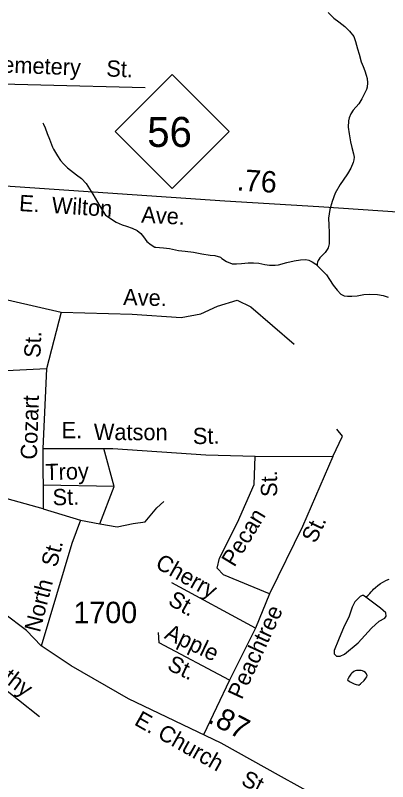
# Model space of a CAD drawing. Extents: x 2056842 to 2160602, y 826753 to 1016856.
# Drawn here: x 2093495 to 2095668, y 860118 to 864586 of the extents above; entities that cross this region are included whole.
import ezdxf

# ---------------------------------------------------------------- set-up
doc = ezdxf.new("R2010")
doc.units = 0
for name, color, linetype in [('Exist Hydrographic Creek Single Shore', 7, 'Continuous'), ('Exist Hydrographic Misc Water Feature', 7, 'Continuous'), ('Exist Road Non-System Type 51', 7, 'Continuous'), ('Exist Road Non-System Type 51 Label', 7, 'Continuous'), ('Exist Road Primary NC Attributed', 7, 'Continuous'), ('Exist Road Primary NC Label', 7, 'Continuous'), ('Exist Road Primary NC Service Mileage Hundredths English Label', 7, 'Continuous'), ('Exist Road Primary NC Shield CELL', 7, 'Continuous'), ('Exist Road Primary NC Shield Number Label', 7, 'Continuous'), ('Exist Road Secondary Mileage Hundredths English Label', 7, 'Continuous'), ('Exist Road Secondary Type 51 Attributed', 7, 'Continuous'), ('Exist Road Secondary Type 51 Label', 7, 'Continuous'), ('Exist Road Secondary Type 51 Number Label', 7, 'Continuous')]:
    doc.layers.add(name, color=color, linetype=linetype)

msp = doc.modelspace()

# ---------------------------------------------------------------- linework, layer by layer
at = {"layer": 'Exist Hydrographic Creek Single Shore'}
for points in [[(2095320, 864601.7), (2095337.8, 864584.4), (2095353.4, 864568.7), (2095383.4, 864549.1), (2095417.4, 864521.2), (2095445.5, 864493.4), (2095469.9, 864463.4), (2095480.1, 864433.4), (2095491.8, 864391.4), (2095502.3, 864359.4), (2095514.2, 864315.9), (2095524.2, 864287.6), (2095534.5, 864261.6), (2095542.3, 864237.7), (2095548.8, 864217.6), (2095550.9, 864191.8), (2095548.8, 864167.7), (2095544.9, 864153.8), (2095531, 864125.9), (2095517.3, 864099.5), (2095499, 864069.4), (2095467, 864033.7), (2095453.3, 864011.5), (2095443.2, 863989.4), (2095439.3, 863971.4), (2095437.7, 863933.4), (2095443.6, 863895.6), (2095451.6, 863849.4), (2095459.6, 863815.6), (2095468, 863779.5), (2095471.9, 863759.4), (2095470.1, 863743.5), (2095466.2, 863727.5), (2095452.5, 863695.5), (2095434, 863661.7), (2095408.4, 863625.4), (2095390.5, 863599.3), (2095362.6, 863549.2), (2095343.2, 863501.4), (2095331.3, 863454.9), (2095323.1, 863403.1), (2095325.3, 863363.3), (2095327.4, 863319.2), (2095327.6, 863285.1), (2095325.7, 863253.3), (2095321.6, 863231.2), (2095315.7, 863221.2), (2095303.8, 863203), (2095281.7, 863182.8), (2095272, 863173), (2095266.1, 863163), (2095262, 863157), (2095257.9, 863147.2), (2095256, 863138.9), (2095256.2, 863127.1)], [(2093655.6, 863960.1), (2093659.9, 863952.1), (2093669.7, 863929.9), (2093681.8, 863898.1), (2093694.1, 863864.1), (2093712.2, 863818), (2093717.9, 863806.2), (2093740.3, 863766.3), (2093758.5, 863740.4), (2093776.4, 863720.2), (2093800.4, 863696.3), (2093852.4, 863656.7), (2093880.5, 863634.7), (2093908.8, 863604.8), (2093947, 863543), (2093989.2, 863472.9), (2094021, 863421), (2094083.1, 863381.1), (2094119.2, 863365.5), (2094143.4, 863357.4), (2094177.4, 863345.3), (2094205.3, 863331.8), (2094227.5, 863313.9), (2094243.7, 863294), (2094261.9, 863268), (2094288, 863247.8), (2094309.9, 863234), (2094315.7, 863233.9), (2094335.7, 863232.1), (2094359.7, 863230.1), (2094395.6, 863226.3), (2094448.1, 863214.3), (2094485.6, 863210.6), (2094534, 863204.5), (2094583.9, 863194.9), (2094631.8, 863187.2), (2094659.9, 863185), (2094691.9, 863175.3), (2094699.7, 863169.2), (2094728.2, 863151.6), (2094759.8, 863137.4), (2094786.2, 863137.4), (2094816, 863139.5), (2094854.1, 863143.8), (2094884.3, 863143.7), (2094916.2, 863142.1), (2094951.7, 863133.8), (2094978, 863130.3), (2094991.9, 863130.2), (2095012, 863130.5), (2095030.1, 863132.2), (2095080.3, 863144.4), (2095121.7, 863154.3), (2095159.9, 863160.8), (2095190, 863162.7), (2095207.8, 863158.7), (2095227.9, 863148.8), (2095248.2, 863134.9), (2095256.2, 863127.1)], [(2095256.2, 863127.1), (2095280, 863104.8), (2095310.2, 863073), (2095328.4, 863045.1), (2095350.3, 863013.5), (2095374.1, 862983.4), (2095394.2, 862961.3), (2095414.3, 862951.3), (2095434.4, 862949.6), (2095458.6, 862949.5), (2095490.4, 862951.6), (2095528.5, 862958), (2095564.4, 862959.8), (2095608.3, 862958.1), (2095642.7, 862952.1), (2095670.2, 862942.2)]]:
    msp.add_lwpolyline(points, dxfattribs=at)
at = {"layer": 'Exist Hydrographic Misc Water Feature'}
for points in [[(2095539.8, 861194), (2095554.2, 861206.1), (2095563.8, 861216), (2095571.6, 861224.2), (2095579.8, 861232.3), (2095585.7, 861240.3), (2095598, 861250.2), (2095611.6, 861262.3), (2095625.9, 861274.3), (2095639.5, 861282.4), (2095661.6, 861292.5), (2095677.4, 861298.6)], [(2095539.8, 861194), (2095527.3, 861204.1), (2095518.4, 861204.1), (2095507, 861197.8), (2095476.7, 861167.4), (2095460.2, 861135.7), (2095441.2, 861077.5), (2095413.3, 861024.2), (2095380.4, 860944.4), (2095355.1, 860882.3), (2095355.1, 860863.3), (2095369, 860849.4), (2095391.8, 860849.4), (2095415.9, 860862.1), (2095495.6, 860928), (2095572.9, 861012.8), (2095618.5, 861053.4), (2095651.4, 861071.1), (2095659, 861083.8), (2095656.5, 861102.8), (2095626.1, 861129.4), (2095539.8, 861194)], [(2095499.1, 860680.5), (2095509, 860688.7), (2095530.9, 860708.5), (2095541, 860722.4), (2095546.5, 860730.5), (2095548.8, 860736.7), (2095546.5, 860740.7), (2095544.5, 860746.6), (2095538.7, 860754.8), (2095528.5, 860760.3), (2095520.7, 860764.4), (2095512.7, 860766.5), (2095504.5, 860766.5), (2095496.9, 860766.4), (2095486.6, 860766.3), (2095478.6, 860764.3), (2095470.8, 860760.7), (2095459, 860750.3), (2095452.8, 860744.3), (2095444.8, 860734.1), (2095436.8, 860720.4), (2095433.1, 860712.4), (2095445, 860702.4), (2095460.6, 860694.4), (2095472.9, 860688.5), (2095485, 860684.7), (2095494.8, 860682.7), (2095499.1, 860680.5)]]:
    msp.add_lwpolyline(points, dxfattribs=at)
at = {"layer": 'Exist Road Non-System Type 51'}
for p, q in [((2093763.4, 862855.8), (2093677.2, 862524.3)), ((2093677.2, 862524.3), (2093656.4, 862060.8)), ((2093656.4, 862060.8), (2093658.5, 861709.6)), ((2094072.8, 861839.5), (2094011.9, 862060.8)), ((2094895.3, 862016.1), (2095347.1, 862015.1)), ((2093987.7, 861621.2), (2094072.8, 861839.5)), ((2093658.5, 861709.6), (2093875.5, 861642)), ((2093875.5, 861642), (2093987.7, 861621.2)), ((2094897.4, 861014.3), (2094409.3, 861278.3)), ((2094978.4, 861213.9), (2094897.4, 861014.3)), ((2094897.4, 861014.3), (2094745.8, 860710.9)), ((2093248.4, 860803.6), (2093635.8, 860499)), ((2094745.8, 860710.9), (2094593.4, 860391.4))]:
    msp.add_line(p, q, dxfattribs=at)
for points in [[(2094253.6, 864164.4), (2093032.2, 864194.9)], [(2092618.3, 863100.9), (2093066.5, 863014.8), (2093763.4, 862855.8)], [(2093763.4, 862855.8), (2094177.7, 862844.4), (2094462.3, 862823.6), (2094577.5, 862845.4), (2094675.2, 862891.2), (2094789.4, 862926.5), (2094870.4, 862887), (2095121.7, 862668.8)], [(2093677.2, 862524.3), (2093131.9, 862498.3), (2092578, 862538.9)], [(2095347.1, 862015.1), (2095405.2, 862133.6), (2095372, 862173.1)], [(2093656.4, 862060.8), (2094063.5, 862060.8), (2094606.6, 862024.5), (2094895.3, 862016.1)], [(2094978.4, 861213.9), (2094710.5, 861324), (2094673.1, 861363.5), (2094687.6, 861421.7), (2094791.5, 861629.6), (2094888.1, 861850.9), (2094895.3, 862016.1)], [(2095347.1, 862015.1), (2095170.5, 861605.6), (2094978.4, 861213.9)], [(2093658.5, 861709.6), (2093039.5, 861880), (2092515.8, 862003.6)], [(2094072.8, 861839.5), (2093657.7, 861846.9)], [(2093987.7, 861621.2), (2094089.4, 861604.6), (2094182.9, 861623.3), (2094253.5, 861633.7), (2094320, 861714.8), (2094361.5, 861752.2)], [(2093875.5, 861642), (2093825.7, 861506.9), (2093646.3, 860909)], [(2094745.8, 860710.9), (2094334.5, 860927), (2094330.4, 860987.3)]]:
    msp.add_lwpolyline(points, dxfattribs=at)
at = {"layer": 'Exist Road Primary NC Attributed'}
msp.add_lwpolyline([(2092795.1, 863628.8), (2092882.4, 863617.4), (2093264, 863603.4), (2094716.8, 863504.7), (2095267.2, 863471.4), (2095984.7, 863422.6), (2096537.2, 863385.2), (2096819.9, 863367.2)], dxfattribs=at)
at = {"layer": 'Exist Road Primary NC Shield CELL'}
msp.add_lwpolyline([(2094078, 863908.6), (2094411, 864241.6), (2094744, 863908.6), (2094411, 863575.6)], close=True, dxfattribs=at)
at = {"layer": 'Exist Road Secondary Type 51 Attributed'}
msp.add_lwpolyline([(2096292.4, 858449.9), (2096015.1, 858656.7), (2095761, 858892.7), (2095692.5, 858988.3), (2095649.6, 859080.7), (2095484.5, 859551.4), (2095411.8, 859807), (2095360.9, 859914.1), (2095309, 859982.7), (2095232.1, 860045), (2095049.4, 860146.8), (2094696.3, 860342.2), (2094155.3, 860601), (2093820.9, 860794.2), (2093645.4, 860909.6), (2093560.2, 860999), (2093425.2, 861100.8), (2093248.7, 861213), (2093084.6, 861298.2), (2092907, 861367.9), (2092581, 861453.1), (2092455.8, 861485.8)], dxfattribs=at)

# ---------------------------------------------------------------- texts
at = {"layer": 'Exist Road Non-System Type 51 Label'}
for s, rotation, p in [('Cemetery', 357.8831, (2093325.7, 864255.8)), ('St.', 357.8831, (2094024.9, 864230)), ('Ave.', 358.5473, (2094123.6, 862897)), ('St.', 87.7014, (2093641, 862588)), ('Cozart', 88.0481, (2093620.5, 861994.8)), ('E. ', 0.0377, (2093765.2, 862120.5)), ('Watson', 359.7121, (2093953, 862110.5)), ('St.', 0.9997, (2094531.8, 862085.9)), ('Troy', 1.6368, (2093671.3, 861875.5)), ('St.', 90.3575, (2095023.3, 861778.7)), ('St.', 1.6368, (2093713.7, 861728.9)), ('Pecan', 58.7419, (2094773.2, 861364.9)), ('St.', 64.7795, (2095247.2, 861503)), ('St.', 75.5423, (2093736.2, 861364.2)), ('Cherry', 330.657, (2094305.8, 861369.1)), ('North', 75.5423, (2093638.3, 860984.5)), ('St.', 330.657, (2094380.1, 861154)), ('Peachtree', 65.2852, (2094816.6, 860592.5)), ('Apple', 334.5187, (2094360, 860956.6)), ('Kathy', 322.9076, (2093291.7, 860803.1)), ('St.', 334.5187, (2094375.7, 860774.1))]:
    msp.add_text(s, height=95, rotation=rotation, dxfattribs=at).set_placement(p)
at = {"layer": 'Exist Road Primary NC Label'}
for s, rotation, p in [('E.  Wilton', 356.3512, (2093515.2, 863445.6)), ('Ave.', 356.8658, (2094228.5, 863378.4))]:
    msp.add_text(s, height=95, rotation=rotation, dxfattribs=at).set_placement(p)
at = {"layer": 'Exist Road Primary NC Service Mileage Hundredths English Label'}
msp.add_text('.76', height=125, rotation=356.1126, dxfattribs=at).set_placement((2094785.2, 863566.1))
at = {"layer": 'Exist Road Primary NC Shield Number Label'}
msp.add_text('56', height=175, dxfattribs=at).set_placement((2094265.1, 863818.9))
at = {"layer": 'Exist Road Secondary Mileage Hundredths English Label'}
msp.add_text('.87', height=125, rotation=332.4378, dxfattribs=at).set_placement((2094612.8, 860466.4))
at = {"layer": 'Exist Road Secondary Type 51 Label'}
for s, rotation, p in [('E. Church', 330.4808, (2094183.7, 860453.3)), ('St.', 333.6233, (2094806.8, 860103.6))]:
    msp.add_text(s, height=95, rotation=rotation, dxfattribs=at).set_placement(p)
at = {"layer": 'Exist Road Secondary Type 51 Number Label'}
msp.add_text('1700', height=125, dxfattribs=at).set_placement((2093834.2, 861042.4))

doc.saveas('drawing.dxf')
